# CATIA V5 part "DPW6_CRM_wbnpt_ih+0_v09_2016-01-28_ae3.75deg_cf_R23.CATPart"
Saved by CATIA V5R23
Part number: DPW6_CRM_wbnpt_ih+0_v09_2016-01-28_ae3
Bounding box of the stored display mesh (mm): x 2349.5 to 66711.883, y -0.001 to 29447.795, z -63.298 to 8715.782
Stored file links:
  C:\Users\mrg\work\AIAA_DPW\DPW6\DLR_meshes\all\3deg75\DPW6_CRM_wbnpt_ih+0_v09_2016-01-28_ae3.75deg_cf_R23.CATPart

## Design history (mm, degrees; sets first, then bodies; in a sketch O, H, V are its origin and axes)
MechanicalRefPlane1 "xy-plane"
MechanicalRefPlane2 "yz-plane"
MechanicalRefPlane3 "zx-plane"
Set1
  DatumSurface1 to DatumSurface3
Body1 (main body)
